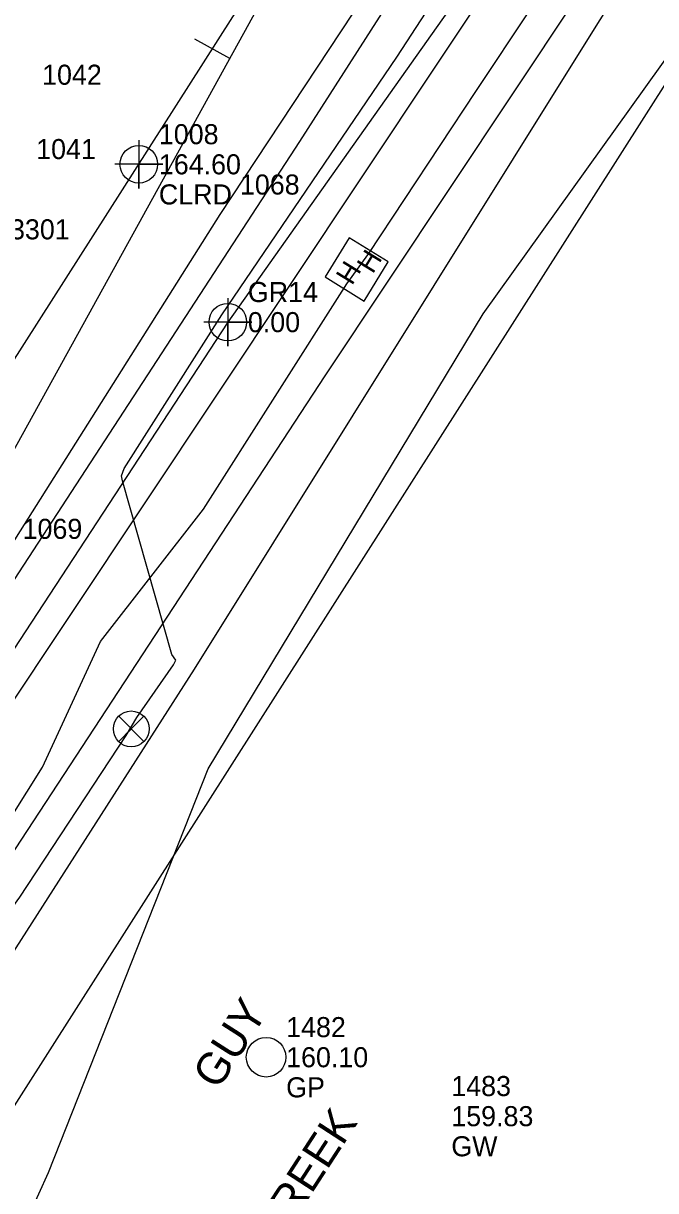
# Model space of a CAD drawing. Extents: x 1840200 to 1849051, y 348278 to 353012.
# Drawn here: x 1844793.7 to 1844872.5, y 350803.3 to 350948.7 of the extents above; entities that cross this region are included whole.
import ezdxf

# ---------------------------------------------------------------- set-up
doc = ezdxf.new("R2010")
doc.units = 0
for name, color, linetype in [('Exist DTM Crownline Cogo Comment', 7, 'Continuous'), ('Exist DTM Crownline Cogo Elevation', 7, 'Continuous'), ('Exist DTM Crownline Cogo Number', 7, 'Continuous'), ('Exist DTM Crownline Cogo Point CELL', 7, 'Continuous'), ('Exist Guardrail', 7, 'Continuous'), ('Exist Guardrail Cogo Comment', 7, 'Continuous'), ('Exist Guardrail Cogo Elevation', 7, 'Continuous'), ('Exist Guardrail Cogo Number', 7, 'Continuous'), ('Exist Guardrail Cogo Point CELL', 7, 'Continuous'), ('Exist Horizontal Alignment', 7, 'Continuous'), ('Exist Horizontal Baseline Alignment', 7, 'Continuous'), ('Exist Horizontal Baseline Alignment Tick small', 7, 'Continuous'), ('Exist Other Culture Anchor (Guy Wire) Cogo Comment', 7, 'Continuous'), ('Exist Other Culture Anchor (Guy Wire) Cogo Elevation', 7, 'Continuous'), ('Exist Other Culture Anchor (Guy Wire) Cogo Number', 7, 'Continuous'), ('Exist Property Line Text', 7, 'Continuous'), ('Exist Right of Way Line', 7, 'Continuous'), ('Exist Roads EOP', 7, 'Continuous'), ('Exist Roads EOP Cogo Number', 7, 'Continuous'), ('Exist Utilities Other Pole CELL', 7, 'Continuous'), ('Exist Utilities Other Pole Cogo Comment', 7, 'Continuous'), ('Exist Utilities Other Pole Cogo Elevation', 7, 'Continuous'), ('Exist Utilities Other Pole Cogo Number', 7, 'Continuous'), ('Exist Utilities Power Pole Text', 7, 'Continuous'), ('Exist Utilities Telephone Hand Hole CELL', 7, 'Continuous'), ('Exist Utilities Telephone UG Cable', 7, 'Continuous'), ('Exist Utilities Telephone UG Conduit SUE', 7, 'Continuous'), ('Exist Utilities Water UG Line SUE', 7, 'Continuous'), ('Exist Utilities Water Valve CELL', 7, 'Continuous'), ('Exist Vegetation Woods Line', 7, 'Continuous')]:
    doc.layers.add(name, color=color, linetype=linetype)

# ---------------------------------------------------------------- blocks, each defined once
blk = doc.blocks.new('EXIST DTM CROWNLINE COGO POINT')
at = {"layer": 'Exist DTM Crownline Cogo Point CELL'}
blk.add_lwpolyline([(0, 0.06), (0, -0.06), (0, 0), (0.06, 0), (-0.06, 0)], dxfattribs=at)
blk.add_circle((0, 0), 0.0469, dxfattribs=at)
blk = doc.blocks.new('EXIST UTILITIES TELEPHONE HAND HOLE')
at = {"layer": 'Exist Utilities Telephone Hand Hole CELL'}
for p, q in [((-0.0573, 0.0573), (-0.0573, -0.0573)), ((0.0573, 0.0573), (-0.0573, 0.0573)), ((0.0573, -0.0573), (0.0573, 0.0573)), ((0, 0), (0, 0)), ((-0.0573, -0.0573), (0.0573, -0.0573))]:
    blk.add_line(p, q, dxfattribs=at)
for p in [(-0.0417, -0.0118), (0.0098, -0.0411)]:
    blk.add_text('H', height=0.05, dxfattribs=at).set_placement(p)
blk = doc.blocks.new('EXIST UTILITIES OTHER POLE')
at = {"layer": 'Exist Utilities Other Pole CELL'}
blk.add_circle((0, 0), 0.0493, dxfattribs=at)

msp = doc.modelspace()

# ---------------------------------------------------------------- linework, layer by layer
at = {"layer": 'Exist Guardrail'}
msp.add_lwpolyline([(1844851.85, 350957.61), (1844819.23, 350911.51), (1844764.37, 350827.75)], dxfattribs=at)
at = {"layer": 'Exist Guardrail Cogo Point CELL'}
msp.add_lwpolyline([(1844819.23, 350914.51), (1844819.23, 350908.51), (1844819.23, 350911.51), (1844822.23, 350911.51), (1844816.23, 350911.51)], dxfattribs=at)
msp.add_circle((1844819.23, 350911.51), 2.34, dxfattribs=at)
at = {"layer": 'Exist Horizontal Alignment'}
msp.add_line((1844418.91, 350320.78), (1844832.24, 350969.01), dxfattribs=at)
at = {"layer": 'Exist Horizontal Baseline Alignment'}
msp.add_line((1844672.71, 350678.49), (1845002.14, 351275.18), dxfattribs=at)
at = {"layer": 'Exist Horizontal Baseline Alignment Tick small'}
msp.add_line((1844819.49, 350944.35), (1844815.12, 350946.77), dxfattribs=at)
at = {"layer": 'Exist Right of Way Line'}
msp.add_line((1844461.07, 350293.9), (1844874.4, 350942.13), dxfattribs=at)
at = {"layer": 'Exist Roads EOP'}
msp.add_lwpolyline([(1845029.44, 351254.68), (1845007.69, 351220.68), (1844980.5, 351178.01), (1844953.56, 351135.84), (1844927.19, 351094.43), (1844899.65, 351051.72), (1844872.25, 351009.01), (1844845.41, 350966.05), (1844818.24, 350924.9), (1844791.16, 350882.01), (1844770.98, 350849.87), (1844762.14, 350830.63)], dxfattribs=at)
at = {"layer": 'Exist Utilities Telephone UG Cable'}
for points in [[(1844781.52, 350847.91), (1844774.84, 350852.19), (1844828.2, 350934), (1844980.52, 351171.7), (1845059.17, 351296.08)], [(1844346.44, 350151.45), (1844341.26, 350155.73), (1844478.11, 350373.12), (1844653.01, 350645.77), (1844660.65, 350640.87), (1844715.71, 350727.83), (1844785.54, 350833.66), (1844790.43, 350842.4), (1844781.52, 350847.91), (1844890.71, 351011.88), (1845027.38, 351230.56), (1845029.36, 351233.76), (1845056.36, 351221.55), (1845032.73, 351239.39), (1845066.03, 351291.24)], [(1844331.53, 350112.62), (1844354.74, 350149.21), (1844815.08, 350868.27), (1844864.7, 350947.73), (1845038.47, 351224.2), (1845056.36, 351221.55), (1845046.68, 351237.02), (1845077.41, 351286.63)], [(1844790.43, 350842.4), (1844831.38, 350904.81), (1844886.06, 350987.05), (1844965.83, 351113.23), (1845037.43, 351227.38), (1845056.36, 351221.55), (1845042.85, 351236.13), (1845074.32, 351286.64)]]:
    msp.add_lwpolyline(points, dxfattribs=at)
at = {"layer": 'Exist Utilities Telephone UG Conduit SUE'}
msp.add_lwpolyline([(1844783.45, 350834.55), (1844784.78, 350838.07), (1844796.15, 350856.09), (1844803.36, 350871.73), (1844816.2, 350888.2), (1844834.06, 350916.27), (1844836.81, 350920.07), (1844850.12, 350940.23), (1844870.69, 350971.18)], dxfattribs=at)
at = {"layer": 'Exist Utilities Water UG Line SUE'}
msp.add_lwpolyline([(1844615.42, 350593.11), (1844652.79, 350651.56), (1844678.12, 350657.97), (1844679, 350658.28), (1844679.2, 350658.91), (1844688.96, 350678.16), (1844703.02, 350703.95), (1844712.42, 350719.28), (1844723.85, 350736.18), (1844772.75, 350811.52), (1844793.33, 350839.86), (1844806.55, 350860.02), (1844807.89, 350862.26), (1844812.47, 350868.84), (1844812.76, 350869.4), (1844812.25, 350870.1), (1844806.09, 350891.76), (1844805.98, 350892.36), (1844806.31, 350893.29), (1844818.47, 350912.44), (1844840.28, 350944.51), (1844863.37, 350979.98)], dxfattribs=at)
at = {"layer": 'Exist Utilities Water Valve CELL'}
msp.add_lwpolyline([(1844808.78, 350862.42), (1844805.63, 350859.27), (1844807.2, 350860.84), (1844808.78, 350859.27), (1844805.63, 350862.42)], dxfattribs=at)
msp.add_circle((1844807.2, 350860.84), 2.23, dxfattribs=at)
at = {"layer": 'Exist Vegetation Woods Line'}
for points in [[(1844796.9, 350805.6), (1844816.79, 350855.86), (1844851.04, 350912.56), (1844897.15, 350976.91), (1844931.29, 351031.99), (1844954.04, 351069.23), (1844985.12, 351120.08), (1845035.99, 351203.55)], [(1845070.01, 350869.81), (1845030.11, 350844.53), (1844978.5, 350807.17), (1844935.82, 350773.29), (1844910.5, 350752.55), (1844892.75, 350732.3), (1844879.25, 350716.15), (1844870.18, 350736.58), (1844881.18, 350775.09), (1844880.17, 350787.58), (1844859.57, 350774.67), (1844839.4, 350706.41), (1844822.64, 350670.45), (1844807.74, 350646.85), (1844790.3, 350647.95), (1844792.72, 350669.3), (1844820.73, 350703.89), (1844816.98, 350750.84), (1844800.41, 350764.51), (1844788.23, 350770.16), (1844784.85, 350775.08), (1844788.4, 350786.96), (1844796.9, 350805.6)]]:
    msp.add_lwpolyline(points, dxfattribs=at)

# ---------------------------------------------------------------- block references
at = {"layer": 'Exist DTM Crownline Cogo Point CELL', "xscale": 50, "yscale": 50}
msp.add_blockref('EXIST DTM CROWNLINE COGO POINT', (1844808.14, 350931.17), dxfattribs=at)
at = {"layer": 'Exist Utilities Other Pole CELL', "xscale": 50, "yscale": 50}
msp.add_blockref('EXIST UTILITIES OTHER POLE', (1844824, 350819.94), dxfattribs=at)
at = {"layer": 'Exist Utilities Telephone Hand Hole CELL', "xscale": 50.00000000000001, "yscale": 50.000000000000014, "rotation": 58.45201035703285}
msp.add_blockref('EXIST UTILITIES TELEPHONE HAND HOLE', (1844835.29, 350918.08), dxfattribs=at)

# ---------------------------------------------------------------- texts
at = {"layer": 'Exist DTM Crownline Cogo Comment'}
msp.add_text('CLRD', height=2.5, dxfattribs=at).set_placement((1844810.64, 350926.17))
at = {"layer": 'Exist DTM Crownline Cogo Elevation'}
msp.add_text('164.60', height=2.5, dxfattribs=at).set_placement((1844810.64, 350929.92))
at = {"layer": 'Exist DTM Crownline Cogo Number'}
msp.add_text('1008', height=2.5, dxfattribs=at).set_placement((1844810.64, 350933.67))
at = {"layer": 'Exist Guardrail Cogo Comment'}
msp.add_text('BL*3301', height=2.5, dxfattribs=at).set_placement((1844786.7, 350921.82))
at = {"layer": 'Exist Guardrail Cogo Elevation'}
msp.add_text('0.00', height=2.5, dxfattribs=at).set_placement((1844821.73, 350910.26))
at = {"layer": 'Exist Guardrail Cogo Number'}
msp.add_text('GR14', height=2.5, dxfattribs=at).set_placement((1844821.73, 350914.01))
at = {"layer": 'Exist Other Culture Anchor (Guy Wire) Cogo Comment'}
msp.add_text('GW', height=2.5, dxfattribs=at).set_placement((1844847.08, 350807.6))
at = {"layer": 'Exist Other Culture Anchor (Guy Wire) Cogo Elevation'}
msp.add_text('159.83', height=2.5, dxfattribs=at).set_placement((1844847.08, 350811.35))
at = {"layer": 'Exist Other Culture Anchor (Guy Wire) Cogo Number'}
msp.add_text('1483', height=2.5, dxfattribs=at).set_placement((1844847.08, 350815.1))
at = {"layer": 'Exist Property Line Text'}
msp.add_text('PL IS C/L OF CREEK', height=4, rotation=57.0205, dxfattribs=at).set_placement((1844807.33, 350768.42))
at = {"layer": 'Exist Roads EOP Cogo Number'}
for s, p in [('1042', (1844796.09, 350941.08)), ('1041', (1844795.35, 350931.82)), ('1068', (1844820.74, 350927.4)), ('1069', (1844793.66, 350884.51))]:
    msp.add_text(s, height=2.5, dxfattribs=at).set_placement(p)
at = {"layer": 'Exist Utilities Other Pole Cogo Comment'}
msp.add_text('GP', height=2.5, dxfattribs=at).set_placement((1844826.5, 350814.94))
at = {"layer": 'Exist Utilities Other Pole Cogo Elevation'}
msp.add_text('160.10', height=2.5, dxfattribs=at).set_placement((1844826.5, 350818.69))
at = {"layer": 'Exist Utilities Other Pole Cogo Number'}
msp.add_text('1482', height=2.5, dxfattribs=at).set_placement((1844826.5, 350822.44))
at = {"layer": 'Exist Utilities Power Pole Text'}
msp.add_text('GUY', height=4, rotation=57.4042, dxfattribs=at).set_placement((1844818.01, 350815.75))

doc.saveas('drawing.dxf')
